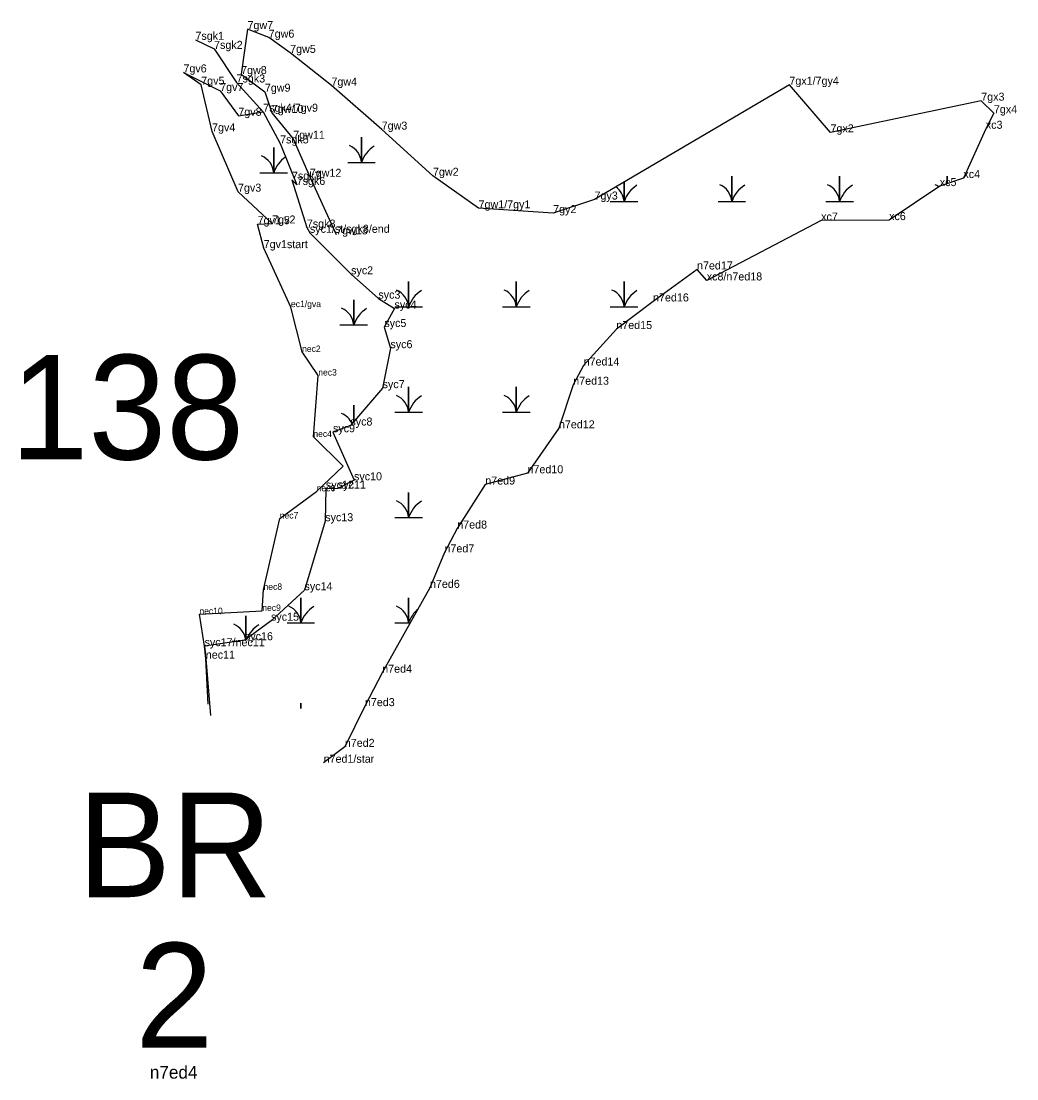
# Model space of a CAD drawing. Extents: x 2072529 to 2268796, y 436423 to 470406.
# Drawn here: x 2162533 to 2163154, y 440111 to 440771 of the extents above; entities that cross this region are included whole.
import ezdxf

# ---------------------------------------------------------------- set-up
doc = ezdxf.new("R2010")
doc.units = 0
for name, color, linetype in [('Default', 7, 'Continuous'), ('Exist Environmental Wetland Boundary', 7, 'Continuous'), ('Exist Environmental Wetland Boundary Cogo Comment', 7, 'Continuous'), ('Exist Hydro Jurisdictional Stream or Body of Water NEU Mitigable', 7, 'Continuous'), ('Exist Hydro Jurisdictional Stream or Body of Water NEU Mitigable Cogo Comment', 7, 'Continuous'), ('Exist Hydro Swamp or Marsh', 7, 'Continuous'), ('Old_Level_20', 7, 'Continuous')]:
    doc.layers.add(name, color=color, linetype=linetype)

msp = doc.modelspace()

# ---------------------------------------------------------------- linework, layer by layer
at = {"layer": 'Exist Environmental Wetland Boundary'}
for points in [[(2163140.04, 440713.98), (2163132.14, 440721.81), (2163038.06, 440702.02), (2163012.38, 440731.78), (2162890.75, 440660.06), (2162864.95, 440651.59), (2162818.4, 440654.59), (2162789.94, 440674.94), (2162757.91, 440703.73), (2162726.54, 440731.21), (2162700.78, 440751.64), (2162687.41, 440761.17), (2162674.17, 440766.47), (2162670.17, 440738.43), (2162685.01, 440727.42), (2162689.37, 440714.14), (2162702.71, 440698), (2162713.04, 440674.27), (2162729.54, 440638.32)], [(2162684.28, 440629.71), (2162680.5, 440644.67), (2162689.6, 440645.11), (2162668.24, 440664.98), (2162652.04, 440702.65), (2162645.3, 440731.79), (2162634.19, 440739.47), (2162657.12, 440727.87), (2162668.45, 440712.38), (2162683.95, 440714.9)], [(2163140.04, 440713.98), (2163135, 440704.26), (2163121, 440673.48), (2163106.24, 440668.46), (2163074.62, 440647.22), (2163032.2, 440646.91), (2162960.82, 440609.54), (2162954.74, 440616.38), (2162927.29, 440596.42), (2162904.37, 440579.19), (2162883.96, 440556.41), (2162877.46, 440544.42), (2162868.56, 440517.19), (2162848.92, 440489.12), (2162822.58, 440482.09), (2162805.07, 440454.59), (2162797.1, 440439.73), (2162788.06, 440417.57), (2162758.24, 440364.57), (2162747.43, 440343.7), (2162734.89, 440318.28), (2162721.69, 440308.34)], [(2162648.13, 440373.35), (2162647.37, 440381.14), (2162644.13, 440401.16), (2162683.38, 440403.16), (2162684.15, 440416.31), (2162694.27, 440460.86), (2162717.3, 440477.83), (2162733.85, 440493.55), (2162715.27, 440511.79), (2162718.33, 440550.16), (2162708.22, 440564.88), (2162701.29, 440592.87), (2162684.28, 440629.71)], [(2162649.66, 440344.94), (2162648.13, 440373.35)]]:
    msp.add_lwpolyline(points, dxfattribs=at)
at = {"layer": 'Exist Hydro Jurisdictional Stream or Body of Water NEU Mitigable'}
for points in [[(2162641.69, 440759.82), (2162653.3, 440754.16), (2162667.33, 440733.17), (2162683.95, 440714.9), (2162694.52, 440695.11), (2162704.85, 440669.2), (2162701.93, 440672.45), (2162711.21, 440642.54)], [(2162711.21, 440642.54), (2162713.1, 440639.3), (2162738.82, 440613.38), (2162755.83, 440598.18), (2162765.92, 440592.01), (2162759.56, 440580.47), (2162763.37, 440567.25), (2162758.48, 440542.29), (2162738.39, 440518.93), (2162727.52, 440514.75), (2162740.64, 440484.73), (2162730.61, 440479.58), (2162723.1, 440479.48), (2162722.69, 440459.2), (2162709.74, 440416.11), (2162688.83, 440397.04), (2162672.57, 440384.85), (2162647.37, 440381.14), (2162648.13, 440373.35), (2162650.98, 440337.75)]]:
    msp.add_lwpolyline(points, dxfattribs=at)
at = {"layer": 'Exist Hydro Swamp or Marsh'}
for points in [[(2162736.69, 440683.25), (2162745.29, 440683.25), (2162745.29, 440699.03), (2162745.29, 440683.25), (2162753.89, 440683.25)], [(2162681.92, 440676.8), (2162690.52, 440676.8), (2162690.52, 440692.58), (2162690.52, 440676.8), (2162699.12, 440676.8)], [(2162967.85, 440658.83), (2162976.45, 440658.83), (2162976.45, 440674.61), (2162976.45, 440658.83), (2162985.05, 440658.83)], [(2163035.1, 440658.83), (2163043.7, 440658.83), (2163043.7, 440674.61), (2163043.7, 440658.83), (2163052.3, 440658.83)], [(2163110.95, 440670.06), (2163110.95, 440674.61), (2163110.95, 440670.06)], [(2162900.6, 440658.83), (2162909.2, 440658.83), (2162909.2, 440670.93)], [(2162909.2, 440670.93), (2162909.2, 440658.83), (2162917.8, 440658.83)], [(2162766.1, 440593.03), (2162774.7, 440593.03), (2162774.7, 440608.81), (2162774.7, 440593.03), (2162783.3, 440593.03)], [(2162833.35, 440593.03), (2162841.95, 440593.03), (2162841.95, 440608.81), (2162841.95, 440593.03), (2162850.55, 440593.03)], [(2162900.6, 440593.03), (2162909.2, 440593.03), (2162909.2, 440608.81), (2162909.2, 440593.03), (2162917.8, 440593.03)], [(2162731.86, 440581.76), (2162740.46, 440581.76), (2162740.46, 440597.54), (2162740.46, 440581.76), (2162749.06, 440581.76)], [(2162766.1, 440527.23), (2162774.7, 440527.23), (2162774.7, 440543.01), (2162774.7, 440527.23), (2162783.3, 440527.23)], [(2162833.35, 440527.23), (2162841.95, 440527.23), (2162841.95, 440543.01), (2162841.95, 440527.23), (2162850.55, 440527.23)], [(2162740.46, 440521.34), (2162740.46, 440531.74), (2162740.46, 440521.34)], [(2162766.1, 440461.43), (2162774.7, 440461.43), (2162774.7, 440477.21), (2162774.7, 440461.43), (2162783.3, 440461.43)], [(2162698.85, 440395.63), (2162707.45, 440395.63), (2162707.45, 440411.41), (2162707.45, 440395.63), (2162716.05, 440395.63)], [(2162766.1, 440395.63), (2162774.7, 440395.63), (2162774.7, 440411.41), (2162774.7, 440395.63), (2162775.72, 440395.63)], [(2162673.21, 440385.33), (2162673.21, 440400.14), (2162673.21, 440385.33)], [(2162664.61, 440384.36), (2162669.19, 440384.36)], [(2162707.45, 440342.22), (2162707.45, 440345.61), (2162707.45, 440342.22)]]:
    msp.add_lwpolyline(points, dxfattribs=at)
for centre, radius, start, end in [((2162733.03, 440682.36), 12.3, 4.14034, 67.53497), ((2162763.53, 440677.19), 19.22, 122.12745, 161.62219), ((2162678.25, 440675.92), 12.3, 4.14034, 67.53497), ((2162708.76, 440670.74), 19.22, 124.36299, 161.62219), ((2162896.93, 440657.95), 12.3, 4.14034, 54.29988), ((2162927.44, 440652.77), 19.22, 122.12745, 161.62219), ((2162964.18, 440657.95), 12.3, 4.14034, 67.53497), ((2162994.69, 440652.77), 19.22, 122.12745, 161.62219), ((2163031.43, 440657.95), 12.3, 4.14034, 67.53497), ((2163061.94, 440652.77), 19.22, 122.12745, 161.62219), ((2163098.68, 440657.95), 12.3, 55.41739, 67.53497), ((2162762.43, 440592.15), 12.3, 4.14034, 67.53497), ((2162792.94, 440586.97), 19.22, 122.12745, 161.62219), ((2162829.68, 440592.15), 12.3, 4.14034, 67.53497), ((2162860.19, 440586.97), 19.22, 122.12745, 161.62219), ((2162896.93, 440592.15), 12.3, 4.14034, 67.53497), ((2162927.44, 440586.97), 19.22, 122.12745, 161.62219), ((2162728.19, 440580.87), 12.3, 4.14034, 67.53497), ((2162758.7, 440575.7), 19.22, 122.12745, 161.62219), ((2162762.43, 440526.35), 12.3, 4.14034, 67.53497), ((2162792.94, 440521.17), 19.22, 122.12745, 161.62219), ((2162829.68, 440526.35), 12.3, 4.14034, 67.53497), ((2162860.19, 440521.17), 19.22, 122.12745, 161.62219), ((2162728.19, 440515.07), 12.3, 24.22304, 67.53497), ((2162762.43, 440460.55), 12.3, 4.14034, 67.53497), ((2162792.94, 440455.37), 19.22, 122.12745, 161.62219), ((2162695.18, 440394.75), 12.3, 4.14034, 67.53497), ((2162725.69, 440389.57), 19.22, 122.12745, 161.62219), ((2162762.43, 440394.75), 12.3, 4.14034, 67.53497), ((2162792.94, 440389.57), 19.22, 129.92973, 161.62219), ((2162660.94, 440383.47), 12.3, 8.36575, 67.53497), ((2162691.45, 440378.3), 19.22, 122.12745, 157.30586)]:
    msp.add_arc(centre, radius, start, end, dxfattribs=at)
at = {"layer": 'Old_Level_20'}
for p, q in [((2162674.17, 440766.47), (2162674.17, 440766.47)), ((2162641.69, 440759.82), (2162641.69, 440759.82)), ((2162687.41, 440761.17), (2162687.41, 440761.17)), ((2162653.3, 440754.16), (2162653.3, 440754.16)), ((2162700.78, 440751.64), (2162700.78, 440751.64)), ((2162634.19, 440739.47), (2162634.19, 440739.47)), ((2162670.17, 440738.43), (2162670.17, 440738.43)), ((2162645.3, 440731.79), (2162645.3, 440731.79)), ((2162667.33, 440733.17), (2162667.33, 440733.17)), ((2162726.54, 440731.21), (2162726.54, 440731.21)), ((2163012.38, 440731.78), (2163012.38, 440731.78)), ((2162657.12, 440727.87), (2162657.12, 440727.87)), ((2162685.01, 440727.42), (2162685.01, 440727.42)), ((2163132.14, 440721.81), (2163132.14, 440721.81)), ((2162668.45, 440712.38), (2162668.45, 440712.38)), ((2162683.95, 440714.9), (2162683.95, 440714.9)), ((2162683.95, 440714.9), (2162683.95, 440714.9)), ((2162689.37, 440714.14), (2162689.37, 440714.14)), ((2163140.04, 440713.98), (2163140.04, 440713.98)), ((2163135, 440704.26), (2163135, 440704.26)), ((2162652.04, 440702.65), (2162652.04, 440702.65)), ((2162702.71, 440698), (2162702.71, 440698)), ((2162757.91, 440703.73), (2162757.91, 440703.73)), ((2163038.06, 440702.02), (2163038.06, 440702.02)), ((2162694.52, 440695.11), (2162694.52, 440695.11)), ((2162701.93, 440672.45), (2162701.93, 440672.45)), ((2162713.04, 440674.27), (2162713.04, 440674.27)), ((2162789.94, 440674.94), (2162789.94, 440674.94)), ((2163121, 440673.48), (2163121, 440673.48)), ((2162668.24, 440664.98), (2162668.24, 440664.98)), ((2162704.85, 440669.2), (2162704.85, 440669.2)), ((2163106.24, 440668.46), (2163106.24, 440668.46)), ((2162890.75, 440660.06), (2162890.75, 440660.06)), ((2162818.4, 440654.59), (2162818.4, 440654.59)), ((2162864.95, 440651.59), (2162864.95, 440651.59)), ((2162680.5, 440644.67), (2162680.5, 440644.67)), ((2162689.6, 440645.11), (2162689.6, 440645.11)), ((2163032.2, 440646.91), (2163032.2, 440646.91)), ((2163074.62, 440647.22), (2163074.62, 440647.22)), ((2162711.21, 440642.54), (2162711.21, 440642.54)), ((2162713.1, 440639.3), (2162713.1, 440639.3)), ((2162729.54, 440638.32), (2162729.54, 440638.32)), ((2162684.28, 440629.71), (2162684.28, 440629.71)), ((2162738.82, 440613.38), (2162738.82, 440613.38)), ((2162954.74, 440616.38), (2162954.74, 440616.38)), ((2162960.82, 440609.54), (2162960.82, 440609.54)), ((2162701.29, 440592.87), (2162701.29, 440592.87)), ((2162755.83, 440598.18), (2162755.83, 440598.18)), ((2162765.92, 440592.01), (2162765.92, 440592.01)), ((2162927.29, 440596.42), (2162927.29, 440596.42)), ((2162759.56, 440580.47), (2162759.56, 440580.47)), ((2162904.37, 440579.19), (2162904.37, 440579.19)), ((2162763.37, 440567.25), (2162763.37, 440567.25)), ((2162708.22, 440564.88), (2162708.22, 440564.88)), ((2162883.96, 440556.41), (2162883.96, 440556.41)), ((2162718.33, 440550.16), (2162718.33, 440550.16)), ((2162758.48, 440542.29), (2162758.48, 440542.29)), ((2162877.46, 440544.42), (2162877.46, 440544.42)), ((2162727.52, 440514.75), (2162727.52, 440514.75)), ((2162738.39, 440518.93), (2162738.39, 440518.93)), ((2162868.56, 440517.19), (2162868.56, 440517.19)), ((2162715.27, 440511.79), (2162715.27, 440511.79)), ((2162848.92, 440489.12), (2162848.92, 440489.12)), ((2162723.1, 440479.48), (2162723.1, 440479.48)), ((2162730.61, 440479.58), (2162730.61, 440479.58)), ((2162740.64, 440484.73), (2162740.64, 440484.73)), ((2162822.58, 440482.09), (2162822.58, 440482.09)), ((2162717.3, 440477.83), (2162717.3, 440477.83)), ((2162694.27, 440460.86), (2162694.27, 440460.86)), ((2162722.69, 440459.2), (2162722.69, 440459.2)), ((2162805.07, 440454.59), (2162805.07, 440454.59)), ((2162797.1, 440439.73), (2162797.1, 440439.73)), ((2162684.15, 440416.31), (2162684.15, 440416.31)), ((2162709.74, 440416.11), (2162709.74, 440416.11)), ((2162788.06, 440417.57), (2162788.06, 440417.57)), ((2162644.13, 440401.16), (2162644.13, 440401.16)), ((2162683.38, 440403.16), (2162683.38, 440403.16)), ((2162688.83, 440397.04), (2162688.83, 440397.04)), ((2162647.37, 440381.14), (2162647.37, 440381.14)), ((2162672.57, 440384.85), (2162672.57, 440384.85)), ((2162648.13, 440373.35), (2162648.13, 440373.35)), ((2162758.24, 440364.57), (2162758.24, 440364.57)), ((2162747.43, 440343.7), (2162747.43, 440343.7)), ((2162734.89, 440318.28), (2162734.89, 440318.28)), ((2162721.69, 440308.34), (2162721.69, 440308.34))]:
    msp.add_line(p, q, dxfattribs=at)

# ---------------------------------------------------------------- texts
at = {"layer": 'Default'}
for s, p in [('138', (2162526.24, 440497.74)), ('BR', (2162568.11, 440224.36)), ('2', (2162604.17, 440130.48))]:
    msp.add_text(s, height=65.34, dxfattribs=at).set_placement(p)
at = {"layer": 'Exist Environmental Wetland Boundary Cogo Comment'}
for s, height, p in [('7gw7', 5, (2162674.17, 440766.47)), ('7gw6', 5, (2162687.41, 440761.17)), ('7gw5', 5, (2162700.78, 440751.64)), ('7gv6', 5, (2162634.19, 440739.47)), ('7gw8', 5, (2162670.17, 440738.43)), ('7gx1/7gy4', 5, (2163012.38, 440731.78)), ('7gv5', 5, (2162645.3, 440731.79)), ('7gv7', 5, (2162657.12, 440727.87)), ('7gw9', 5, (2162685.01, 440727.42)), ('7gw4', 5, (2162726.54, 440731.21)), ('7gx3', 5, (2163132.14, 440721.81)), ('7gv8', 5, (2162668.45, 440712.38)), ('7gw10', 5, (2162689.37, 440714.14)), ('7gx4', 5, (2163140.04, 440713.98)), ('7gv4', 5, (2162652.04, 440702.65)), ('7gw3', 5, (2162757.91, 440703.73)), ('7gx2', 5, (2163038.06, 440702.02)), ('xc3', 5, (2163135, 440704.26)), ('7gw11', 5, (2162702.71, 440698)), ('7gw12', 5, (2162713.04, 440674.27)), ('7gw2', 5, (2162789.94, 440674.94)), ('xc4', 5, (2163121, 440673.48)), ('xc5', 5, (2163106.24, 440668.46)), ('7gv3', 5, (2162668.24, 440664.98)), ('7gy3', 5, (2162890.75, 440660.06)), ('7gw1/7gy1', 5, (2162818.4, 440654.59)), ('7gy2', 5, (2162864.95, 440651.59)), ('xc7', 5, (2163032.2, 440646.91)), ('xc6', 5, (2163074.62, 440647.22)), ('7gv1.5', 5, (2162680.5, 440644.67)), ('7gv2', 5, (2162689.6, 440645.11)), ('7gw13', 5, (2162729.54, 440638.32)), ('7gv1start', 5, (2162684.28, 440629.71)), ('n7ed17', 5, (2162954.74, 440616.38)), ('xc8/n7ed18', 5, (2162960.82, 440609.54)), ('n7ed16', 5, (2162927.29, 440596.42)), ('ec1/gva', 4, (2162701.29, 440592.87)), ('n7ed15', 5, (2162904.37, 440579.19)), ('nec2', 4, (2162708.22, 440564.88)), ('n7ed14', 5, (2162883.96, 440556.41)), ('nec3', 4, (2162718.33, 440550.16)), ('n7ed13', 5, (2162877.46, 440544.42)), ('n7ed12', 5, (2162868.56, 440517.19)), ('nec4', 4, (2162715.27, 440511.79)), ('n7ed10', 5, (2162848.92, 440489.12)), ('n7ed9', 5, (2162822.58, 440482.09)), ('nec6', 4, (2162717.3, 440477.83)), ('nec7', 4, (2162694.27, 440460.86)), ('n7ed8', 5, (2162805.07, 440454.59)), ('n7ed7', 5, (2162797.1, 440439.73)), ('nec8', 4, (2162684.15, 440416.31)), ('n7ed6', 5, (2162788.06, 440417.57)), ('nec9', 4, (2162683.38, 440403.16)), ('nec10', 4, (2162644.13, 440401.16)), ('nec11', 5, (2162648.13, 440373.35)), ('n7ed4', 5, (2162758.24, 440364.57)), ('n7ed3', 5, (2162747.43, 440343.7)), ('n7ed2', 5, (2162734.89, 440318.28)), ('n7ed1/star', 5, (2162721.69, 440308.34)), ('n7ed4', 8, (2162613.2, 440111.06))]:
    msp.add_text(s, height=height, dxfattribs=at).set_placement(p)
at = {"layer": 'Exist Hydro Jurisdictional Stream or Body of Water NEU Mitigable Cogo Comment'}
for s, p in [('7sgk1', (2162641.69, 440759.82)), ('7sgk2', (2162653.3, 440754.16)), ('7sgk3', (2162667.33, 440733.17)), ('7sgk4/7gv9', (2162683.95, 440714.9)), ('7sgk4', (2162683.95, 440714.9)), ('7sgk5', (2162694.52, 440695.11)), ('7sgk7', (2162701.93, 440672.45)), ('7sgk6', (2162704.85, 440669.2)), ('7sgk8', (2162711.21, 440642.54)), ('syc1/st/sgk8/end', (2162713.1, 440639.3)), ('syc2', (2162738.82, 440613.38)), ('syc3', (2162755.83, 440598.18)), ('syc4', (2162765.92, 440592.01)), ('syc5', (2162759.56, 440580.47)), ('syc6', (2162763.37, 440567.25)), ('syc7', (2162758.48, 440542.29)), ('syc9', (2162727.52, 440514.75)), ('syc8', (2162738.39, 440518.93)), ('syc10', (2162740.64, 440484.73)), ('syc12', (2162723.1, 440479.48)), ('syc11', (2162730.61, 440479.58)), ('syc13', (2162722.69, 440459.2)), ('syc14', (2162709.74, 440416.11)), ('syc15', (2162688.83, 440397.04)), ('syc16', (2162672.57, 440384.85)), ('syc17/nec11', (2162647.37, 440381.14))]:
    msp.add_text(s, height=5, dxfattribs=at).set_placement(p)

doc.saveas('drawing.dxf')
